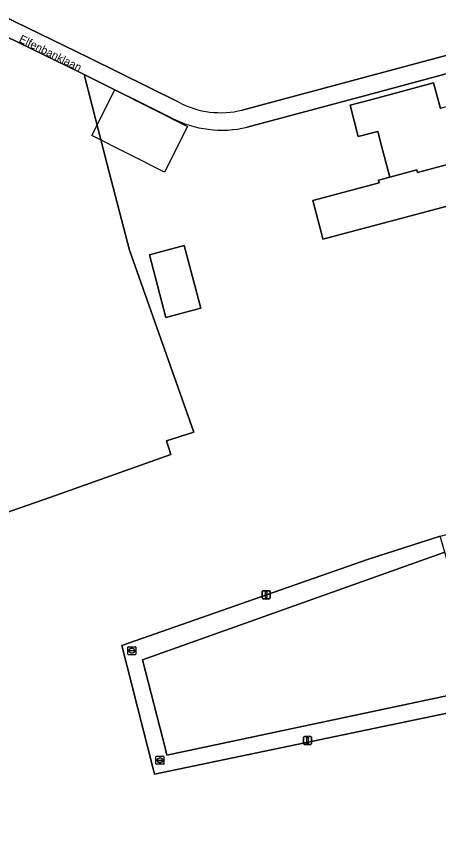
# Model space of a CAD drawing. Extents: x 162661 to 163484, y 380247 to 381230.
# Drawn here: x 162779.1 to 162831.7, y 380630.3 to 380734.1 of the extents above; entities that cross this region are included whole.
import ezdxf

# ---------------------------------------------------------------- set-up
doc = ezdxf.new("R2010")
doc.units = 0
for name, color, linetype in [('IMGEO_Erf', 7, 'Continuous'), ('IMGEO_Groenvoorziening', 7, 'Continuous'), ('IMGEO_Hek', 7, 'Continuous'), ('IMGEO_Lichtmast', 7, 'Continuous'), ('IMGEO_Loofbos', 7, 'Continuous'), ('IMGEO_Openbare_ruimte_label', 7, 'Continuous'), ('IMGEO_Pand', 7, 'Continuous'), ('IMGEO_Pand_vergunning_verleend', 7, 'Continuous'), ('IMGEO_Rioolput', 7, 'Continuous'), ('IMGEO_Voetpad_open', 7, 'Continuous')]:
    doc.layers.add(name, color=color, linetype=linetype)

msp = doc.modelspace()

# ---------------------------------------------------------------- linework, layer by layer
at = {"layer": 'IMGEO_Erf'}
for points in [[(162858.87, 380689.77), (162847.76, 380730.99), (162822.96, 380724.29), (162807.84, 380720.25)], [(162798.38, 380721.42), (162787.52, 380726.82), (162790.41, 380715.6), (162793.16, 380704.88), (162801.19, 380682.16), (162797.79, 380681.08), (162798.32, 380679.38), (162783.25, 380674.01), (162743.23, 380660.08), (162747.47, 380643.78), (162754.58, 380617.79)], [(162832.83, 380710.38), (162825.6, 380708.47), (162817.31, 380706.29), (162817.26, 380706.48), (162817.08, 380707.15), (162816.04, 380711.11), (162824.33, 380713.3), (162824.24, 380713.64), (162825.64, 380714.01), (162824.44, 380718.56), (162824.35, 380718.91), (162824.14, 380719.71), (162821.72, 380719.08), (162820.69, 380722.99), (162823.11, 380723.64), (162831.12, 380725.77), (162831.96, 380722.6)], [(162857.18, 380583.08), (162855.17, 380582.54), (162855.09, 380582.84), (162854.26, 380585.89), (162815.61, 380577.39), (162813.56, 380576.83), (162810.05, 380589.99), (162849.43, 380603.92), (162849.52, 380603.6), (162851.48, 380604.11), (162851.35, 380604.6), (162839.36, 380648.57), (162837.58, 380648.1), (162796.31, 380639.47), (162796.14, 380640.12), (162792.21, 380655.52), (162822.87, 380666.27), (162831.95, 380669.19), (162832.26, 380669.29), (162839.83, 380671.31), (162839.12, 380673.77), (162839.44, 380673.83), (162838.83, 380676.05)]]:
    msp.add_lwpolyline(points, dxfattribs=at)
msp.add_lwpolyline([(162797.73, 380696.5), (162795.66, 380704.33), (162800.02, 380705.48), (162802.08, 380697.65)], close=True, dxfattribs=at)
msp.add_arc((162804.69, 380733.56), 13.68, 242.5403, 283.3349, dxfattribs=at)
at = {"layer": 'IMGEO_Groenvoorziening'}
msp.add_lwpolyline([(162743.23, 380660.08), (162783.25, 380674.01), (162798.32, 380679.38), (162797.79, 380681.08), (162801.19, 380682.16), (162793.16, 380704.88), (162790.41, 380715.6), (162787.52, 380726.82), (162787.02, 380727.08), (162756.23, 380742.12)], dxfattribs=at)
msp.add_lwpolyline([(162832.52, 380667.2), (162794.8, 380653.76), (162797.65, 380642.61), (162797.84, 380641.85), (162837.06, 380650.17), (162836.74, 380651.46), (162832.88, 380665.85)], close=True, dxfattribs=at)
at = {"layer": 'IMGEO_Hek'}
for points in [[(162787.52, 380726.82), (162790.41, 380715.6)], [(162790.41, 380715.6), (162793.16, 380704.88), (162801.19, 380682.16), (162797.79, 380681.08), (162798.32, 380679.38), (162783.25, 380674.01)]]:
    msp.add_lwpolyline(points, dxfattribs=at)
at = {"layer": 'IMGEO_Lichtmast'}
for p, q in [((162809.73, 380661.48), (162809.73, 380662.28)), ((162809.73, 380662.28), (162809.73, 380661.48)), ((162809.83, 380662.38), (162810.62, 380662.38)), ((162810.62, 380662.38), (162809.83, 380662.38)), ((162810.72, 380662.28), (162810.72, 380661.48)), ((162810.72, 380661.48), (162810.72, 380662.28)), ((162810.62, 380661.38), (162809.83, 380661.38)), ((162809.83, 380661.38), (162810.62, 380661.38)), ((162814.9, 380643.28), (162814.9, 380644.08)), ((162814.9, 380644.08), (162814.9, 380643.28)), ((162815, 380644.18), (162815.79, 380644.18)), ((162815.79, 380644.18), (162815, 380644.18)), ((162815.89, 380644.08), (162815.89, 380643.28)), ((162815.89, 380643.28), (162815.89, 380644.08)), ((162815.79, 380643.18), (162815, 380643.18)), ((162815, 380643.18), (162815.79, 380643.18))]:
    msp.add_line(p, q, dxfattribs=at)
for points in [[(162810.15, 380662.26), (162810.3, 380662.26), (162810.3, 380661.51), (162810.15, 380661.51), (162810.15, 380662.26)], [(162815.32, 380644.05), (162815.47, 380644.05), (162815.47, 380643.3), (162815.32, 380643.3), (162815.32, 380644.05)]]:
    msp.add_lwpolyline(points, dxfattribs=at)
for centre, start, end in [((162809.83, 380662.28), 90, 180), ((162809.83, 380662.28), 90, 180), ((162810.62, 380662.28), 0, 90), ((162810.62, 380662.28), 360, 90), ((162809.83, 380661.48), 180, 270), ((162809.83, 380661.48), 180, 270), ((162810.62, 380661.48), 270, 0), ((162810.62, 380661.48), 270, 0), ((162815, 380644.08), 90, 180), ((162815, 380644.08), 90, 180), ((162815.79, 380644.08), 0, 90), ((162815.79, 380644.08), 360, 90), ((162815, 380643.28), 180, 270), ((162815, 380643.28), 180, 270), ((162815.79, 380643.28), 270, 0), ((162815.79, 380643.28), 270, 0)]:
    msp.add_arc(centre, 0.1, start, end, dxfattribs=at)
at = {"layer": 'IMGEO_Loofbos'}
for points in [[(162822.93, 380816.8), (162822.01, 380816.55), (162760.54, 380800.32), (162760.65, 380799.92), (162738.34, 380790.32), (162737.81, 380781.91), (162734.35, 380774.31), (162733.6, 380755.87), (162744.86, 380750), (162788.16, 380728.91), (162799.32, 380723.36)], [(162807.25, 380722.39), (162841.32, 380731.52), (162845.6, 380732.65), (162822.93, 380816.8)]]:
    msp.add_lwpolyline(points, dxfattribs=at)
msp.add_arc((162804.56, 380733.23), 11.17, 242.0363, 283.9484, dxfattribs=at)
at = {"layer": 'IMGEO_Pand'}
for points in [[(162837.96, 380724.19), (162834.02, 380723.14), (162832.57, 380722.76), (162832.21, 380722.67), (162831.96, 380722.6), (162831.12, 380725.77), (162823.11, 380723.64), (162820.69, 380722.99), (162821.72, 380719.08), (162824.14, 380719.71), (162824.35, 380718.91), (162824.44, 380718.56), (162825.64, 380714.01), (162829.02, 380714.91), (162829.11, 380714.59), (162835.95, 380716.41), (162838.13, 380716.99), (162839.76, 380717.43)], [(162842.97, 380715.18), (162838.9, 380714.1), (162836.72, 380713.51), (162835.95, 380716.41), (162829.11, 380714.59), (162829.02, 380714.91), (162825.64, 380714.01), (162824.24, 380713.64), (162824.33, 380713.3), (162816.04, 380711.11), (162817.08, 380707.15), (162817.26, 380706.48), (162817.31, 380706.29), (162825.6, 380708.47), (162832.83, 380710.38), (162834.12, 380705.6), (162839.94, 380707.14), (162844.78, 380708.43)], [(162795.66, 380704.33), (162797.73, 380696.5), (162802.08, 380697.65), (162800.02, 380705.48)]]:
    msp.add_lwpolyline(points, close=True, dxfattribs=at)
at = {"layer": 'IMGEO_Pand_vergunning_verleend'}
msp.add_lwpolyline([(162788.46, 380719.21), (162791.33, 380724.92), (162800.42, 380720.35), (162797.54, 380714.64)], close=True, dxfattribs=at)
at = {"layer": 'IMGEO_Rioolput'}
for p, q in [((162793.04, 380655.39), (162793.9, 380655.39)), ((162792.97, 380654.46), (162792.97, 380655.32)), ((162793.9, 380654.39), (162793.04, 380654.39)), ((162793.23, 380654.88), (162793.23, 380654.9)), ((162793.27, 380654.93), (162793.67, 380654.93)), ((162793.67, 380654.85), (162793.27, 380654.85)), ((162793.46, 380655.17), (162793.48, 380655.17)), ((162793.48, 380654.61), (162793.46, 380654.61)), ((162793.71, 380654.9), (162793.71, 380654.88)), ((162793.97, 380655.32), (162793.97, 380654.46)), ((162796.48, 380640.77), (162796.48, 380641.62)), ((162796.56, 380641.7), (162797.41, 380641.7)), ((162796.74, 380641.19), (162796.74, 380641.2)), ((162797.18, 380641.15), (162796.78, 380641.15)), ((162796.79, 380641.24), (162797.18, 380641.24)), ((162796.97, 380641.48), (162797, 380641.48)), ((162796.99, 380640.92), (162796.97, 380640.92)), ((162797.23, 380641.2), (162797.23, 380641.19)), ((162797.48, 380641.62), (162797.48, 380640.77)), ((162797.41, 380640.7), (162796.56, 380640.7))]:
    msp.add_line(p, q, dxfattribs=at)
for points in [[(162793.04, 380655.39), (162793.9, 380655.39)], [(162792.97, 380654.46), (162792.97, 380655.32)], [(162793.9, 380654.39), (162793.04, 380654.39)], [(162793.97, 380655.32), (162793.97, 380654.46)], [(162796.48, 380640.77), (162796.48, 380641.62)], [(162796.56, 380641.7), (162797.41, 380641.7)], [(162797.48, 380641.62), (162797.48, 380640.77)], [(162797.41, 380640.7), (162796.56, 380640.7)]]:
    msp.add_lwpolyline(points, dxfattribs=at)
for centre, radius, start, end in [((162793.05, 380655.31), 0.0765, 91.552, 178.448), ((162793.05, 380655.31), 0.0765, 91.552, 178.448), ((162793.89, 380655.31), 0.0765, 1.552, 88.448), ((162793.89, 380655.31), 0.0765, 1.552, 88.448), ((162793.05, 380654.47), 0.0765, 181.552, 268.448), ((162793.05, 380654.47), 0.0765, 181.552, 268.448), ((162793.27, 380654.89), 0.0403, 85.8775, 175.7526), ((162793.27, 380654.88), 0.0366, 178.938, 274.7102), ((162793.67, 380654.89), 0.0386, 1.7309, 96.639), ((162793.67, 380654.89), 0.043, 264.8664, 352.4533), ((162793.89, 380654.47), 0.0765, 271.552, 358.448), ((162793.89, 380654.47), 0.0765, 271.552, 358.448), ((162796.56, 380641.62), 0.0765, 91.552, 178.448), ((162796.56, 380641.62), 0.0765, 91.552, 178.448), ((162796.78, 380641.2), 0.0403, 85.8775, 175.7526), ((162796.78, 380641.19), 0.0366, 178.938, 274.7102), ((162797.19, 380641.2), 0.0386, 1.7309, 96.639), ((162797.18, 380641.2), 0.043, 264.8664, 352.4533), ((162797.41, 380641.62), 0.0765, 1.552, 88.448), ((162797.41, 380641.62), 0.0765, 1.552, 88.448), ((162796.56, 380640.77), 0.0765, 181.552, 268.448), ((162796.56, 380640.77), 0.0765, 181.552, 268.448), ((162797.41, 380640.77), 0.0765, 271.552, 358.448), ((162797.41, 380640.77), 0.0765, 271.552, 358.448)]:
    msp.add_arc(centre, radius, start, end, dxfattribs=at)
for centre, major_axis, ratio, start_param, end_param in [((162793.46, 380654.89), (-0.387, 0.002), 0.722429, 4.712389, 7.853982), ((162793.48, 380654.89), (-0.39, 0.002), 0.717154, 1.570796, 4.712389), ((162796.97, 380641.2), (-0.387, 0.002), 0.722429, 4.712389, 7.853982), ((162796.99, 380641.2), (-0.39, 0.002), 0.717154, 1.570796, 4.712389)]:
    msp.add_ellipse(centre, major_axis=major_axis, ratio=ratio, start_param=start_param, end_param=end_param, dxfattribs=at)
at = {"layer": 'IMGEO_Voetpad_open'}
for points in [[(162744.86, 380750), (162733.6, 380755.87), (162731.75, 380756.84), (162728.08, 380758.66), (162720.43, 380762.64), (162719.14, 380760.93), (162725.18, 380757.75), (162732.52, 380754.04), (162740.21, 380750), (162751.66, 380744.36), (162756.23, 380742.12), (162787.02, 380727.08), (162787.52, 380726.82), (162798.38, 380721.42)], [(162799.32, 380723.36), (162788.16, 380728.91), (162744.86, 380750)], [(162807.84, 380720.25), (162822.96, 380724.29), (162847.76, 380730.99), (162845.6, 380732.65), (162841.32, 380731.52), (162807.25, 380722.39)]]:
    msp.add_lwpolyline(points, dxfattribs=at)
msp.add_lwpolyline([(162794.8, 380653.76), (162832.52, 380667.2), (162831.95, 380669.19), (162822.87, 380666.27), (162792.21, 380655.52), (162796.14, 380640.12), (162796.31, 380639.47), (162837.58, 380648.1), (162837.06, 380650.17), (162797.84, 380641.85), (162797.65, 380642.61)], close=True, dxfattribs=at)
for centre, radius, start, end in [((162804.56, 380733.23), 11.17, 242.0363, 283.9484), ((162804.69, 380733.56), 13.68, 242.5403, 283.3349)]:
    msp.add_arc(centre, radius, start, end, dxfattribs=at)

# ---------------------------------------------------------------- texts
at = {"layer": 'IMGEO_Openbare_ruimte_label'}
msp.add_text('Elfenbanklaan', height=1, rotation=333.6399, dxfattribs=at).set_placement((162779.3, 380730.94))

doc.saveas('drawing.dxf')
